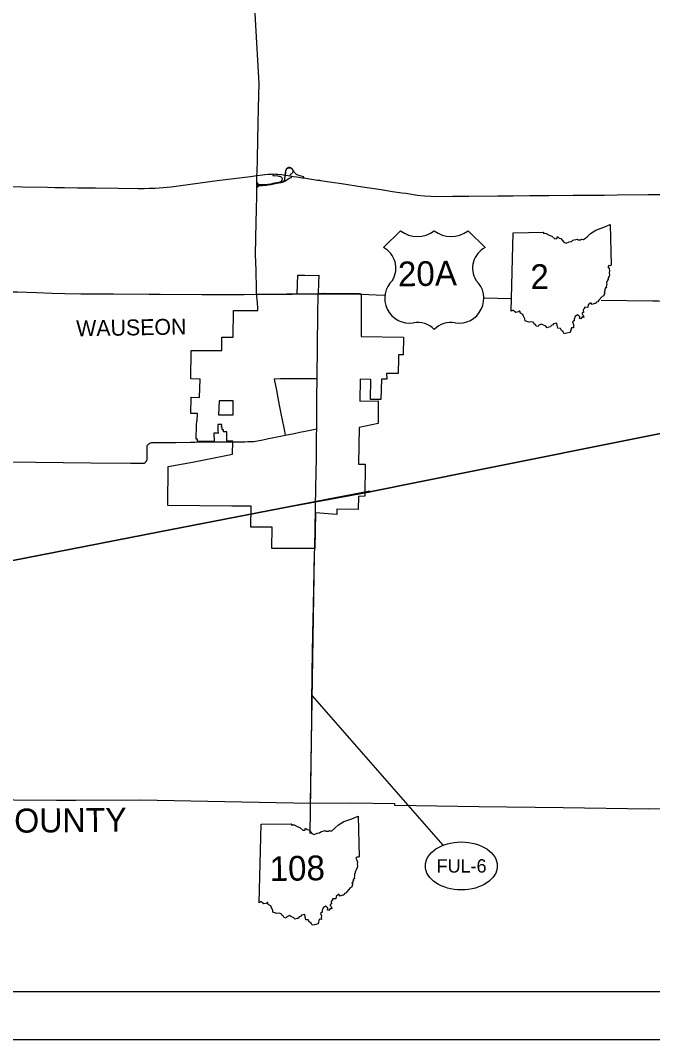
# Model space of a CAD drawing. Extents: x 0 to 849, y 0 to 440.
# Drawn here: x 267.5 to 399.3, y 0 to 212.6 of the extents above; entities that cross this region are included whole.
import ezdxf

# ---------------------------------------------------------------- set-up
doc = ezdxf.new("R2010")
doc.units = 0
for name, color, linetype in [('DV_X_Corp_Line', 7, 'Continuous'), ('GM_X_Adjacent_County_Text', 7, 'Continuous'), ('GM_X_Corporation_Text', 7, 'Continuous'), ('GM_X_County', 7, 'Continuous'), ('GM_X_Interchange_Ramps', 7, 'Continuous'), ('GM_X_Interstate_Route', 7, 'Continuous'), ('PV_P_Walk', 7, 'Continuous'), ('RD_X_RR_2', 7, 'Continuous'), ('SH_Border', 7, 'Continuous'), ('SH_Cut_Line', 7, 'Continuous'), ('SH_Data', 7, 'Continuous')]:
    doc.layers.add(name, color=color, linetype=linetype)

msp = doc.modelspace()

# ---------------------------------------------------------------- linework, layer by layer
at = {"layer": 'DV_X_Corp_Line'}
for points in [[(338.25, 133.19), (342.03, 133.21), (342.03, 128.48), (338.13, 127.66), (337.97, 120.06), (339.35, 120.05), (339.26, 113.32), (337.93, 113.3), (337.88, 110.55), (333.47, 110.64), (333.42, 109.52), (328.97, 109.85), (328.88, 102.42), (324.51, 102.42), (319.88, 102.44), (319.98, 106.92), (315.51, 106.89), (315.6, 111.24), (311.53, 111.29), (298.23, 111.41), (298.29, 119.56), (303.34, 120.45), (311.72, 122.11), (311.74, 124.79), (310.5, 124.79), (310.52, 126.74), (309.8, 126.77), (309.79, 127.21), (309.57, 127.2), (309.56, 127.71), (309.43, 127.71), (309.45, 128.28), (308.65, 128.31), (308.61, 127.36), (308.62, 127.14), (308.64, 126.88), (308.69, 126.65), (308.74, 126.5), (307.82, 126.49), (307.88, 124.77), (307.42, 124.76), (304.4, 124.75), (304.4, 125.25), (304.1, 125.25), (304.2, 128.19), (304.23, 129.01), (304.23, 129.06), (304.35, 129.12), (304.37, 130.58), (303.01, 130.6), (303.06, 133.98), (304.84, 133.95), (304.92, 137.78), (303.02, 137.8), (303.06, 143.76), (309.47, 143.75), (309.48, 146.55), (311.82, 146.53), (311.88, 152.08), (316.98, 152.09), (316.94, 152.46), (316.87, 153.86), (316.84, 154.25), (316.73, 155.22), (316.73, 155.53), (317.7, 155.52), (318.56, 155.51), (322.93, 155.56), (325.18, 155.6), (325.3, 159.46), (326.73, 159.48), (326.74, 159.38), (329.69, 159.42), (329.64, 157.87), (329.58, 155.65), (330.64, 155.66), (330.81, 155.66), (334.12, 155.64), (337.73, 155.6), (338.18, 155.6), (338.53, 155.59), (338.54, 146.63), (347.36, 146.52), (347.3, 142.82), (346.32, 142.85), (346.31, 142.24), (346.23, 138.93), (343.83, 138.95), (343.84, 137.73), (342.75, 137.75), (342.62, 133.51), (340.44, 133.54), (340.51, 137.68), (338.34, 137.74)], [(308.76, 130.32), (311.81, 130.32), (311.84, 133.21), (308.93, 133.27)]]:
    msp.add_lwpolyline(points, close=True, dxfattribs=at)
at = {"layer": 'GM_X_County'}
msp.add_lwpolyline([(407.4, 48.26), (398.5, 48.1), (380.63, 48.35), (363.06, 48.58), (345.56, 48.83), (345.56, 49.15), (336.3, 49.3), (327.98, 49.28), (310.1, 49.61), (292.41, 49.95), (279.01, 49.89), (275.02, 49.87), (274.97, 49.87), (257.21, 50.03)], dxfattribs=at)
at = {"layer": 'GM_X_Interchange_Ramps'}
for points in [[(326.56, 179.73), (326.59, 179.98), (326.01, 180.11), (325.56, 180.22), (325.32, 180.3), (325.17, 180.37), (325.01, 180.47), (324.89, 180.57), (324.74, 180.7), (324.64, 180.83), (324.54, 180.98), (324.26, 181.43), (324.15, 181.6), (324.05, 181.71), (323.94, 181.79), (323.82, 181.86), (323.66, 181.9), (323.5, 181.9), (323.35, 181.88), (323.21, 181.83), (323.08, 181.75), (322.97, 181.65), (322.88, 181.53), (322.82, 181.42), (322.77, 181.27), (322.71, 180.8), (322.65, 180.32), (322.6, 179.87), (322.56, 179.64), (322.54, 179.52), (322.5, 179.36), (322.45, 179.24), (322.39, 179.12), (322.31, 179.04), (322.24, 178.99), (322.1, 178.9), (321.93, 178.86), (321.72, 178.81), (321.54, 178.78), (321.53, 178.82)], [(322.3, 178.92), (322.29, 178.95), (322.39, 179.03), (322.46, 179.11), (322.51, 179.2), (322.57, 179.33), (322.6, 179.48), (322.7, 180.31), (322.77, 180.85), (322.81, 181.19), (322.86, 181.37), (322.92, 181.48), (322.98, 181.59), (323.05, 181.66), (323.15, 181.74), (323.26, 181.8), (323.38, 181.84), (323.53, 181.86), (323.64, 181.85), (323.78, 181.83), (323.89, 181.77), (324, 181.7), (324.08, 181.62), (324.15, 181.52), (324.2, 181.42), (324.25, 181.27), (324.26, 181.15), (324.24, 181.01), (324.21, 180.87), (324.12, 180.73), (324.02, 180.6), (323.88, 180.5), (323.76, 180.44), (323.69, 180.42), (323.66, 180.16)], [(316.76, 177.81), (316.89, 177.81), (317, 177.93), (317.09, 178.02), (317.17, 178.08), (317.3, 178.13), (317.32, 178.14), (317.39, 178.16), (317.5, 178.17), (317.92, 178.18), (318.41, 178.22), (318.71, 178.25), (319.1, 178.3), (319.66, 178.39), (320.3, 178.52), (320.9, 178.63), (321.84, 178.79), (322.14, 178.85), (322.3, 178.92), (322.35, 178.94), (322.58, 179.07), (322.86, 179.25), (323.42, 179.61), (323.6, 179.71), (323.73, 179.76), (323.85, 179.79), (324, 179.81), (324.04, 180.11)], [(320.15, 180.56), (320.13, 180.25), (320.36, 180.24), (321.15, 180.15), (321.36, 180.13), (321.54, 180.08), (321.69, 180.03), (321.8, 179.95), (321.9, 179.87), (321.97, 179.76), (322.01, 179.61), (322.02, 179.44), (322, 179.31), (321.97, 179.19), (321.89, 179.1), (321.78, 178.99), (321.62, 178.86), (321.53, 178.82), (321.38, 178.8), (320.93, 178.69), (320.12, 178.55), (319.71, 178.46), (319.07, 178.37), (318.44, 178.3), (317.54, 178.26), (317.36, 178.27), (317.32, 178.28), (317.24, 178.31), (317.15, 178.38), (317.06, 178.46), (316.99, 178.54), (316.94, 178.64), (316.77, 178.65)], [(317.32, 178.28), (317.31, 178.26), (316.9, 178.25), (316.77, 178.25)], [(316.77, 178.17), (316.9, 178.17), (317.31, 178.17), (317.32, 178.14)]]:
    msp.add_lwpolyline(points, dxfattribs=at)
at = {"layer": 'GM_X_Interstate_Route'}
for points in [[(317.06, 190.95), (317.12, 194.28), (317.22, 199.46), (315.73, 226.19)], [(316.81, 180.93), (316.9, 183.59), (316.96, 187.84), (317.06, 190.95)], [(316.79, 180.23), (316.81, 180.93)], [(261.71, 177.94), (267.92, 177.85), (273.14, 177.77), (274.64, 177.76), (276.66, 177.72), (279.36, 177.69), (282, 177.64), (283.15, 177.64), (287.82, 177.58), (291.99, 177.53), (293.28, 177.54), (294.32, 177.57), (295.59, 177.62), (298.89, 177.9), (308.46, 179.16), (315.44, 180.05), (316.79, 180.23)], [(316.77, 178.25), (316.77, 178.65), (316.79, 180.23)], [(316.79, 180.23), (317.95, 180.36), (318.41, 180.44), (319.11, 180.51), (319.81, 180.54), (320.15, 180.56), (320.65, 180.54), (321.16, 180.51), (321.98, 180.42), (322.65, 180.32), (322.7, 180.31), (323.31, 180.21)], [(323.31, 180.21), (323.66, 180.16), (324.04, 180.11), (324.37, 180.06)], [(324.37, 180.06), (325.02, 179.95), (325.54, 179.88), (326.24, 179.77), (326.56, 179.73), (328.6, 179.42), (329.44, 179.29), (329.84, 179.23), (330.07, 179.2), (332.38, 178.86), (334.41, 178.55), (338.76, 177.89), (342.67, 177.29), (345.04, 176.93), (347.02, 176.63), (347.82, 176.52), (350.28, 176.15), (351.69, 176.02), (353.07, 175.92), (354.32, 175.89), (357.64, 175.91), (358.74, 175.92), (360.99, 175.94), (367.02, 175.99), (370.21, 176.01), (373.65, 176.04), (377.61, 176.07), (382.71, 176.12), (383.2, 176.12), (383.75, 176.12), (386.18, 176.15), (387.93, 176.16), (389.23, 176.17), (391.88, 176.19), (398.36, 176.25), (400.9, 176.28)], [(316.7, 155.48), (316.68, 156.43), (316.59, 160.51), (316.5, 163.79), (316.63, 170.52), (316.71, 173.08), (316.75, 176.13), (316.75, 176.54)], [(316.75, 176.54), (316.76, 177.81), (316.77, 178.17), (316.77, 178.25)], [(246.72, 156), (253.77, 155.97), (256.58, 155.99), (259.15, 156), (264.38, 155.97), (266.86, 155.96), (270.84, 155.82), (274.09, 155.71), (276.76, 155.61), (280.09, 155.59), (286.89, 155.53), (294.34, 155.48), (296.6, 155.47), (305.33, 155.42), (310.78, 155.43), (310.81, 155.43)], [(310.81, 155.43), (314.07, 155.44), (314.1, 155.44)], [(314.1, 155.44), (316.53, 155.48)], [(316.53, 155.48), (316.7, 155.48)], [(316.7, 155.48), (319.52, 155.49)], [(319.52, 155.49), (324.21, 155.52), (325.14, 155.53)], [(325.14, 155.53), (326.72, 155.54), (326.73, 155.54)], [(326.73, 155.54), (327.42, 155.55), (327.43, 155.55)], [(327.43, 155.55), (328.83, 155.57), (328.84, 155.57)], [(328.84, 155.57), (329.54, 155.58)], [(329.32, 137.82), (329.41, 144.82), (329.48, 151.08), (329.54, 155.58)], [(329.54, 155.58), (331.67, 155.55), (331.67, 155.55)], [(331.67, 155.55), (338.27, 155.47), (338.59, 155.46)], [(338.59, 155.46), (341.62, 155.35), (343.61, 155.25)], [(364.25, 154.7), (369.65, 154.59)], [(388.53, 154.24), (399.3, 154.12), (400.49, 154.11), (415.39, 154.05), (418.14, 154.05), (420.96, 154)], [(328.27, 137.82), (326.52, 137.84), (324.92, 137.83), (321.68, 137.8), (320.41, 137.79)], [(320.41, 137.79), (320.85, 135.44), (321.15, 133.86), (321.45, 132.34), (321.78, 130.58), (322.11, 128.91), (322.29, 127.97)], [(329.32, 137.82), (328.27, 137.82)], [(329.3, 134.17), (329.32, 137.82)], [(329.24, 127.37), (329.26, 128.78), (329.27, 128.96), (329.28, 130.61), (329.28, 131.55), (329.3, 134.05), (329.3, 134.17)], [(322.29, 127.97), (322.5, 126.93)], [(311.76, 124.71), (313.99, 124.72), (314.27, 124.72), (314.9, 124.73), (316.1, 124.75), (316.13, 124.76), (318.01, 125.13), (319.19, 125.37), (320.29, 125.59), (320.96, 125.73)], [(320.96, 125.73), (321.32, 125.8), (322.68, 126.07)], [(322.5, 126.93), (322.5, 126.93), (322.68, 126.07)], [(322.68, 126.07), (324.58, 126.45)], [(324.58, 126.45), (325.73, 126.68), (326.87, 126.9), (329.24, 127.37)], [(329.17, 119.96), (329.17, 120.07), (329.17, 120.13), (329.18, 122.05), (329.19, 123.77), (329.19, 123.78), (329.21, 125.39), (329.22, 126), (329.24, 127.37)], [(276.4, 120.37), (282.18, 120.3), (290.44, 120.25), (293.27, 120.25), (293.45, 120.38), (293.67, 120.58), (293.82, 120.81), (293.88, 120.98), (293.93, 123.92), (294.03, 124.07), (294.26, 124.29), (294.48, 124.42), (294.83, 124.56), (299.86, 124.54), (302.93, 124.64), (302.93, 124.64)], [(302.93, 124.64), (302.97, 124.64), (303.82, 124.65), (304.71, 124.66), (304.71, 124.66)], [(304.71, 124.66), (306.13, 124.67), (306.14, 124.67)], [(306.14, 124.67), (307.84, 124.69), (309.35, 124.7), (310.7, 124.7), (310.7, 124.7)], [(310.7, 124.7), (311.76, 124.71)], [(242.74, 120.69), (249.83, 120.66), (256.91, 120.58), (258.65, 120.56), (264.84, 120.5), (276.4, 120.37)], [(329.01, 111.45), (329.07, 114.57), (329.15, 118.62), (329.16, 119.25)], [(329.16, 119.25), (329.16, 119.61), (329.17, 119.96)], [(328.98, 110.04), (329, 111.28), (329.01, 111.33), (329.01, 111.45)], [(328.91, 106.67), (328.92, 107.36), (328.97, 109.85), (328.98, 110.04)], [(328.84, 102.6), (328.91, 106.67)], [(328.82, 101.36), (328.84, 102.42), (328.84, 102.6), (328.84, 102.6)], [(328.3, 75.41), (328.31, 76.47), (328.46, 84.7), (328.59, 90.52), (328.82, 101.36), (328.82, 101.36)], [(327.89, 42.98), (328.22, 66.96), (328.26, 71.01), (328.3, 75.41)]]:
    msp.add_lwpolyline(points, dxfattribs=at)
at = {"layer": 'PV_P_Walk'}
for p, q in [((346.71, 168.73), (343.16, 165.19)), ((364.34, 165.19), (360.8, 168.73)), ((369.77, 151.91), (370.23, 168.29)), ((317.23, 28.55), (317.69, 44.92))]:
    msp.add_line(p, q, dxfattribs=at)
for points in [[(370.23, 168.29), (376.59, 168.39), (376.49, 168.2), (377.09, 168.15), (377.72, 167.81), (378.26, 167.58), (378.92, 167.06), (379.31, 167.07), (379.48, 167.5), (379.78, 167.17), (380.14, 167.11), (380.76, 166.32), (381.27, 166.15), (381.88, 166.42), (382.34, 166.47), (382.68, 166.73), (383.55, 166.96), (383.79, 166.82), (384.25, 166.85), (384.48, 166.95), (384.89, 166.86), (385.6, 167.46), (386.33, 168.16), (387.45, 168.82), (389.12, 169.45), (390.45, 170.01), (390.64, 161.51)], [(390.64, 161.51), (390.44, 161.39), (390.14, 161.45), (389.93, 161.21), (390.19, 160.81), (390.31, 160.39), (390.2, 159.93), (390.31, 159.55), (390.24, 159.23), (390.04, 158.91), (389.98, 158.61), (389.82, 158.29), (389.83, 158.11), (389.67, 157.97), (389.7, 157.44), (389.62, 157.14), (389.65, 156.89), (389.4, 156.82), (389.46, 156.61), (389.3, 156.45), (389.33, 156.17), (389.15, 155.99), (389.33, 155.64), (389.18, 155.52), (389.07, 155.09), (388.74, 155), (388.1, 154.21), (387.87, 153.91), (387.61, 153.83), (387.47, 153.53), (387.16, 153.53), (386.68, 153.31), (386.37, 153.68), (385.83, 153.24), (385.77, 152.73), (385.09, 152.74), (385.11, 152.49), (384.96, 152.41), (384.82, 152.15), (384.9, 151.69), (384.58, 151.57), (384.62, 151.31), (384.82, 151.14), (384.92, 150.63), (384.58, 150.74), (384.3, 150.31), (384.01, 150.41), (384.1, 150.77), (383.62, 151.21), (383.16, 150.86), (382.92, 150.3), (382.92, 149.92), (382.58, 149.7), (382.8, 149.16), (382.76, 148.8), (382.77, 148.45), (382.34, 148.46), (382.08, 147.52)], [(382.08, 147.52), (381.34, 147.34), (380.83, 147.23), (380.64, 147.66), (380.28, 147.89), (380.04, 148.32), (379.51, 148.37), (379.38, 148.96), (379.32, 149.44), (378.6, 149.32), (378.4, 149.03), (378.15, 148.95), (378, 148.66), (377.65, 148.63), (377.27, 148.49), (377.03, 148.78), (376.41, 149.07), (376.14, 149.22), (375.56, 148.99), (375.44, 148.72), (374.98, 148.84), (374.87, 149.14), (374.59, 149.24), (374.53, 149.56), (373.94, 149.74), (373.48, 149.67), (372.68, 149.93), (372.63, 150.36), (372.36, 150.88), (372.21, 151.25), (371.71, 151.52), (371.61, 151.95), (371.44, 151.94), (371.29, 151.77), (370.73, 151.69), (370.51, 151.86), (370.19, 152.16), (369.77, 151.91)], [(317.69, 44.92), (324.04, 45.03), (323.94, 44.83), (324.54, 44.79), (325.18, 44.44), (325.72, 44.22), (326.38, 43.7), (326.77, 43.7), (326.94, 44.13), (327.24, 43.8), (327.6, 43.74), (328.22, 42.96), (328.73, 42.79), (329.34, 43.06), (329.8, 43.1), (330.13, 43.37), (331, 43.59), (331.25, 43.46), (331.71, 43.49), (331.94, 43.59), (332.34, 43.5), (333.05, 44.09), (333.78, 44.79), (334.9, 45.46), (336.58, 46.08), (337.9, 46.64), (338.1, 38.15)], [(338.1, 38.15), (337.9, 38.03), (337.59, 38.08), (337.39, 37.85), (337.64, 37.45), (337.76, 37.03), (337.66, 36.57), (337.76, 36.18), (337.69, 35.86), (337.5, 35.55), (337.43, 35.24), (337.27, 34.92), (337.28, 34.74), (337.13, 34.6), (337.16, 34.07), (337.08, 33.78), (337.11, 33.52), (336.85, 33.46), (336.91, 33.25), (336.75, 33.08), (336.79, 32.8), (336.6, 32.63), (336.78, 32.27), (336.64, 32.16), (336.52, 31.72), (336.2, 31.64), (335.55, 30.84), (335.33, 30.54), (335.07, 30.47), (334.93, 30.16), (334.61, 30.16), (334.14, 29.95), (333.83, 30.31), (333.29, 29.87), (333.22, 29.36), (332.54, 29.38), (332.57, 29.12), (332.41, 29.04), (332.28, 28.79), (332.36, 28.33), (332.04, 28.21), (332.08, 27.94), (332.28, 27.78), (332.37, 27.27), (332.03, 27.37), (331.75, 26.94), (331.47, 27.04), (331.56, 27.41), (331.08, 27.84), (330.62, 27.49), (330.38, 26.93), (330.38, 26.56), (330.04, 26.33), (330.25, 25.8), (330.21, 25.43), (330.22, 25.08), (329.79, 25.09), (329.54, 24.15)], [(329.54, 24.15), (328.79, 23.97), (328.28, 23.87), (328.1, 24.29), (327.73, 24.52), (327.49, 24.95), (326.96, 25.01), (326.84, 25.6), (326.78, 26.08), (326.06, 25.96), (325.86, 25.67), (325.6, 25.59), (325.45, 25.29), (325.1, 25.27), (324.73, 25.13), (324.48, 25.42), (323.87, 25.71), (323.59, 25.86), (323.02, 25.63), (322.89, 25.35), (322.43, 25.47), (322.33, 25.78), (322.05, 25.87), (321.99, 26.2), (321.39, 26.37), (320.94, 26.3), (320.13, 26.56), (320.09, 26.99), (319.81, 27.52), (319.67, 27.88), (319.16, 28.16), (319.06, 28.59), (318.9, 28.58), (318.75, 28.4), (318.19, 28.32), (317.96, 28.5), (317.65, 28.8), (317.23, 28.55)]]:
    msp.add_lwpolyline(points, dxfattribs=at)
for centre, radius, start, end in [((350.23, 173.21), 5.7, 231.813, 308.187), ((357.27, 173.21), 5.7, 231.813, 308.187), ((340.94, 160.91), 4.82, 329.1175, 62.6108), ((366.56, 160.91), 4.82, 117.3892, 210.8825), ((348.63, 154.63), 5.2, 133.0046, 278.7282), ((358.88, 154.63), 5.2, 261.2718, 46.9954), ((350.37, 144.94), 4.65, 43.4177, 101.8742), ((357.23, 144.63), 4.94, 79.9613, 134.7468)]:
    msp.add_arc(centre, radius, start, end, dxfattribs=at)
at = {"layer": 'RD_X_RR_2'}
for points in [[(454.53, 137.21), (443.43, 134.93), (399.52, 126.15), (361.72, 118.55), (340.35, 114.29), (340.38, 114.29)], [(340.38, 114.29), (340.35, 114.29), (361.72, 118.55), (399.52, 126.15), (443.43, 134.93), (454.74, 137.17)], [(340.35, 114.38), (323.72, 111.19), (296.49, 105.88), (265.55, 99.86), (241.52, 95.04), (226.11, 92), (226.13, 92.01)], [(226.11, 92), (241.52, 95.04), (265.55, 99.86), (296.49, 105.88), (323.72, 111.19), (340.38, 114.29)]]:
    msp.add_lwpolyline(points, dxfattribs=at)
at = {"layer": 'SH_Border'}
msp.add_lwpolyline([(30, 430), (670, 430), (670, 10), (30, 10)], close=True, dxfattribs=at)
at = {"layer": 'SH_Cut_Line'}
msp.add_lwpolyline([(0, 0), (680, 0), (680, 440), (0, 440)], close=True, dxfattribs=at)
at = {"layer": 'SH_Data'}
for p, q in [((327.98, 49.28), (328.82, 101.06)), ((355.63, 40.55), (328.34, 71.74))]:
    msp.add_line(p, q, dxfattribs=at)
msp.add_ellipse((359.4, 36.23), major_axis=(7.5, 0), ratio=0.666667, dxfattribs=at)

# ---------------------------------------------------------------- texts
at = {"layer": 'GM_X_Adjacent_County_Text'}
msp.add_text('HENRY COUNTY', height=5.0058, rotation=0.5197, dxfattribs=at).set_placement((236.08, 42.88))
at = {"layer": 'GM_X_Corporation_Text'}
msp.add_text('WAUSEON', height=3.325, rotation=1.0142, dxfattribs=at).set_placement((279.13, 146.68))
at = {"layer": 'PV_P_Walk'}
for s, p in [('20A', (346.23, 157.1)), (' 2 ', (371.93, 156.5)), ('108', (319.48, 33.06))]:
    msp.add_text(s, height=5.162, rotation=1.0142, dxfattribs=at).set_placement(p)
at = {"layer": 'SH_Data'}
msp.add_text('FUL-6', height=2.8, dxfattribs=at).set_placement((354.25, 34.83))

doc.saveas('drawing.dxf')
